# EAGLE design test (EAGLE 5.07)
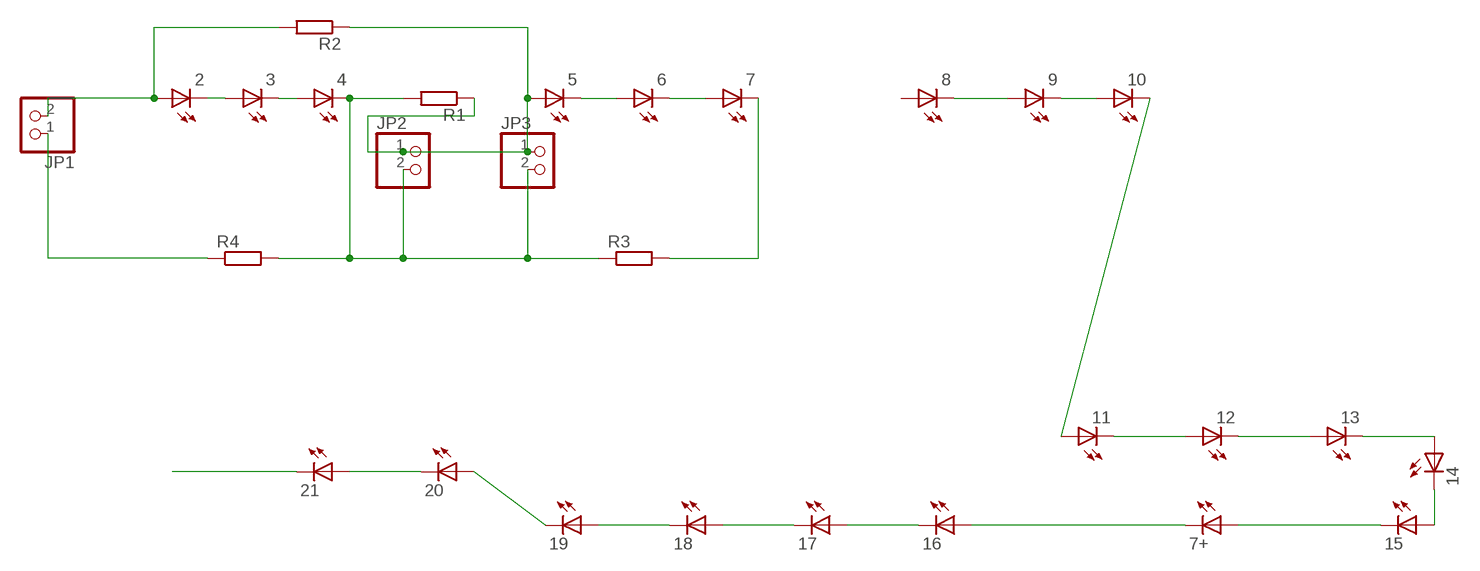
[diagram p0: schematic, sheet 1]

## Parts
2  LED1210  [1210]
3  LED1210  [1210]
4  LED1210  [1210]
5  LED1210  [1210]
6  LED1210  [1210]
7  LED1210  [1210]
7+  LED1210  [1210]
8  LED1210  [1210]
9  LED1210  [1210]
10  LED1210  [1210]
11  LED1210  [1210]
12  LED1210  [1210]
13  LED1210  [1210]
14  LED1210  [1210]
15  LED1210  [1210]
16  LED1210  [1210]
17  LED1210  [1210]
18  LED1210  [1210]
19  LED1210  [1210]
20  LED1210  [1210]
21  LED1210  [1210]
JP1  PINHD-1X2  [1X02X05]
JP2  PINHD-1X2  [1X02X05]
JP3  PINHD-1X2  [1X02X05]
R1  R-EU_R0603  [R0603]
R2  R-EU_R0603  [R0603]
R3  R-EU_R0603  [R0603]
R4  R-EU_R0603  [R0603]

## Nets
7: 7.P$2(C) R3.2
MINUS: 21.P$2(C)
N$1: 2.P$1(A) JP1.2 R2.2
N$2: 20.P$2(C) 21.P$1(A)
N$3: 4.P$2(C) JP2.2 JP3.2 R1.2 R3.1 R4.2
N$4: 19.P$2(C) 20.P$1(A)
N$5: JP1.1 R4.1
N$7: 18.P$2(C) 19.P$1(A)
N$8: 17.P$2(C) 18.P$1(A)
N$9: 16.P$2(C) 17.P$1(A)
N$12: 7+.P$1(A) 15.P$2(C)
N$13: 7+.P$2(C) 16.P$1(A)
N$14: 14.P$2(C) 15.P$1(A)
N$15: 13.P$2(C) 14.P$1(A)
N$16: 12.P$2(C) 13.P$1(A)
N$17: 11.P$2(C) 12.P$1(A)
N$18: 10.P$2(C) 11.P$1(A)
N$19: 9.P$2(C) 10.P$1(A)
N$20: 8.P$2(C) 9.P$1(A)
N$23: 6.P$2(C) 7.P$1(A)
N$24: 5.P$2(C) 6.P$1(A)
N$25: 5.P$1(A) JP2.1 JP3.1 R1.1 R2.1
N$26: 2.P$2(C) 3.P$1(A)
N$28: 3.P$2(C) 4.P$1(A)
Unconnected: 8.P$1(A)

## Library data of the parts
2-7 7+ 8-21 = led(2):LED: LED
JP1-JP3 = pinhead:PINHD-1X2: PIN HEADER
R1-R4 = rcl:R-EU_: RESISTOR, European symbol

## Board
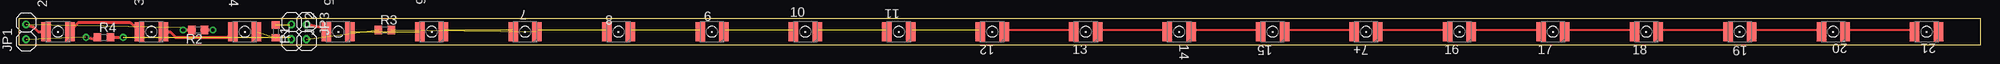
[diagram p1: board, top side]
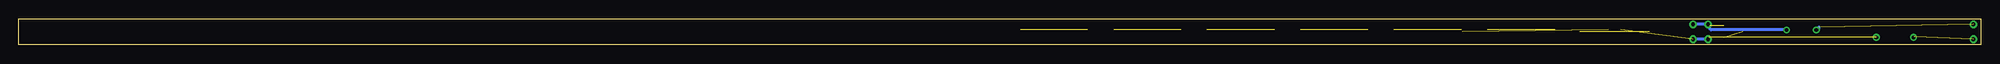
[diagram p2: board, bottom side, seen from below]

Size 262.5 x 3.5 mm. Coordinates in mm from the lower left corner, seen from the top.
Outline: 0,0 262.5,0 262.5,3.5 0,3.5 0,0
Copper layers (1*16): Top 0.035mm / dielectric 1.5mm / Bottom 0.035mm
Design rules "default": minimum track width 10mil, minimum drill 24mil, track to track 8mil, track to pad 8mil, pad to pad 8mil, via to via 8mil, smd to smd 8mil, copper to edge 40mil, drill to drill 8mil, minimum pad ring 10mil, minimum via ring 8mil, stop-mask expansion 4mil, vias tented up to drill 0mil, thermal gap 10mil

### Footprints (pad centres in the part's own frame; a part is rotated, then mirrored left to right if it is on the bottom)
1210 = smd 1.27 x 2.54: P$1 1.587,0; P$2 -1.587,0
1X02X05 = drill 0.5 pad 0.813 round: 1 -1,0; 2 1,0
R0603 = smd 1 x 1.1: 1 -0.85,0; 2 0.85,0

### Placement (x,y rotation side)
2  5.25,1.75 180 top
3  17.75,1.75 180 top
4  30.25,1.75 180 top
5  42.75,1.75 180 top
6  55.25,1.75 180 top
7  67.75,1.75 180 top
7+  180.25,1.75 180 top
8  80.25,1.75 180 top
9  92.75,1.75 180 top
10  105.25,1.75 180 top
11  117.75,1.75 180 top
12  130.25,1.75 180 top
13  142.75,1.75 180 top
14  155.25,1.75 180 top
15  167.75,1.75 180 top
16  192.75,1.75 180 top
17  205.25,1.75 180 top
18  217.75,1.75 180 top
19  230.25,1.75 180 top
20  242.75,1.75 180 top
21  255.25,1.75 180 top
JP1  1,1.75 90 top
JP2  36.5,1.75 270 top
JP3  38.5,1.75 270 top
R1  34.4,1.8 270 top
R2  24,2 180 top
R3  49,2 0 top
R4  11.4,1 0 top

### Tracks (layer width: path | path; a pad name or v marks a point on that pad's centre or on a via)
7  (2 unrouted)
  Top 0.254: 7.P$2 69.5,2
N$1  (via drill 0.5 pad 0.41)  (1 unrouted)
  Top 0.406: v22,2 R2.2 | 2.P$1 2.63,1.75 2,2.38 JP1.2
  Bottom 0.406: 21.61,2.38 v22,2
N$2
  Top 0.254: 20.P$2 244.5,2 253.5,2 21.P$1
N$3  (via drill 0.5 pad 0.41)  (4 unrouted)
  Top 0.406: R4.2 v14,1
  Bottom 0.406: 36.38,1 JP2.2 JP3.2
N$4
  Top 0.254: 19.P$2 232,2 241,2 20.P$1
N$5  (via drill 0.5 pad 0.41)  (1 unrouted)
  Top 0.406: v9,1 10,0.85 R4.1
  Bottom 0.406: 8.88,1.11 v9,1
N$7
  Top 0.254: 18.P$2 219.5,2 228.5,2 19.P$1
N$8
  Top 0.254: 17.P$2 207,2 216,2 18.P$1
N$9
  Top 0.254: 16.P$2 194.5,2 203.5,2 17.P$1
N$12
  Top 0.254: 15.P$2 169.5,2 178.5,2 7+.P$1
N$13
  Top 0.254: 7+.P$2 182,2 191,2 16.P$1
N$14
  Top 0.254: 14.P$2 157,2 166,2 15.P$1
N$15
  Top 0.254: 13.P$2 144.5,2 153.5,2 14.P$1
N$16
  Top 0.254: 12.P$2 132,2 141,2 13.P$1
N$17  (1 unrouted)
  Top 0.254: 11.P$2 119.5,2 | 128.5,2 12.P$1
N$18  (1 unrouted)
  Top 0.254: 10.P$2 107,2 | 116,2 11.P$1
N$19  (1 unrouted)
  Top 0.254: 9.P$2 94.5,2 | 103.5,2 10.P$1
N$20  (1 unrouted)
  Top 0.254: 8.P$2 82,2 | 91,2 9.P$1
N$23  (1 unrouted)
  Top 0.254: 6.P$2 57,2 | 66,2 7.P$1
N$24  (1 unrouted)
N$25  (via drill 0.5 pad 0.41)  (1 unrouted)
  Top 0.406: JP2.1 36.23,2.65 | JP3.1 40.53,2.38 5.P$1 | R2.1 v26,2
  Bottom 0.406: JP3.1 JP2.1 36.12,2 v26,2
N$26
  Top 0.406: 2.P$2 6.84,1.84 8,3 14.91,3 3.P$1
N$28
  Top 0.406: 3.P$2 20.25,1.75 21,1 27.91,1 4.P$1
